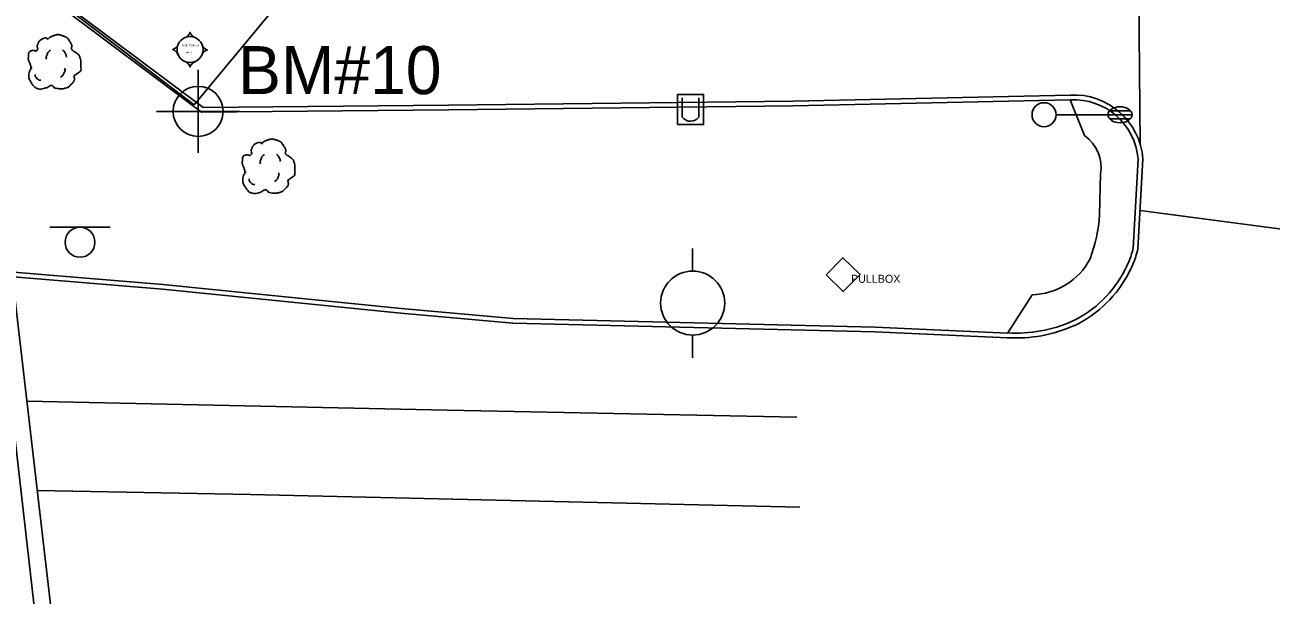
# Model space of a CAD drawing. Extents: x 2145380 to 2156929, y 139568 to 149130.
# Drawn here: x 2147386.4 to 2147542.1, y 143177.2 to 143248.5 of the extents above; entities that cross this region are included whole.
import ezdxf

# ---------------------------------------------------------------- set-up
doc = ezdxf.new("R2010")
doc.units = 0
for name, color, linetype in [('Default', 7, 'Continuous'), ('SURV_Benchmark', 7, 'Continuous'), ('SURV_Text', 7, 'Continuous'), ('TOPO_Asphalt', 7, 'Continuous'), ('TOPO_Concrete', 7, 'Continuous'), ('TOPO_Curb Back', 7, 'Continuous'), ('TOPO_Light Pole', 7, 'Continuous'), ('TOPO_Misc', 7, 'Continuous'), ('TOPO_Misc Line', 7, 'Continuous'), ('TOPO_Monitoring Well', 7, 'Continuous'), ('TOPO_Power Pole', 7, 'Continuous'), ('TOPO_Power Pullbox', 7, 'Continuous'), ('TOPO_Sidewalk', 7, 'Continuous'), ('TOPO_Sign', 7, 'Continuous'), ('TOPO_Tree', 7, 'Continuous')]:
    doc.layers.add(name, color=color, linetype=linetype)

# ---------------------------------------------------------------- blocks, each defined once
blk = doc.blocks.new('LP')
at = {"layer": 'TOPO_Light Pole'}
blk.add_line((3.81, 0), (20.32, 0), dxfattribs=at)
for points in [[(20.32, 0), (27.94, 0)], [(20.32, 0), (23.5, 0)], [(20.83, 1.27), (27.43, 1.27)], [(20.83, 1.27), (23.5, 1.27)], [(23.71, 1.27), (27.43, 1.27)], [(23.71, 0), (27.94, 0)], [(20.83, -1.27), (27.43, -1.27)], [(20.83, -1.27), (23.5, -1.27)], [(23.71, -1.27), (27.43, -1.27)]]:
    blk.add_lwpolyline(points, dxfattribs=at)
blk.add_circle((0, 0), 3.81, dxfattribs=at)
blk.add_ellipse((24.13, 0), major_axis=(3.81, 0), ratio=0.666667, dxfattribs=at)
blk = doc.blocks.new('TREE')
at = {"layer": 'TOPO_Tree'}
for points in [[(-14.07, -0.4), (-14.17, 0.5), (-14.37, 1.38), (-14.6, 2.25), (-14.84, 3.17), (-15.47, 3.96), (-15.66, 4.9), (-15.8, 5.59), (-15.71, 6.31), (-15.66, 7.01), (-15.6, 7.91), (-15.72, 8.8), (-15.13, 9.66), (-14.62, 10.42), (-13.76, 10.49), (-13.02, 10.72), (-12.18, 10.98), (-11.06, 10), (-10.37, 10.72), (-9.4, 11.74), (-10.29, 13.28), (-9.84, 14.42), (-9.56, 15.15), (-9.32, 15.89), (-8.78, 16.54), (-8.18, 17.26), (-7.5, 17.68), (-6.67, 18.13), (-6.14, 18.41), (-5.61, 18.61), (-5.08, 18.66), (-4.55, 18.71), (-4.02, 18.54), (-3.49, 18.13)], [(-3.49, 17.6), (-3.07, 18.27), (-2.58, 18.8), (-1.9, 19.19), (-1.05, 19.68), (-0.19, 19.96), (0.74, 20.24), (1.62, 20.51), (2.51, 20.82), (3.39, 20.77), (4.1, 20.73), (4.8, 20.47), (5.51, 20.24), (6.43, 19.95), (7.32, 19.73), (8.15, 19.19), (9.36, 18.4), (10.02, 17.21), (10.8, 16.01), (11.24, 15.33), (11.58, 14.62), (11.86, 13.89), (12.17, 13.08), (11.37, 12.02), (11.86, 11.25), (12, 11.03), (12.18, 10.86), (12.39, 10.72), (12.91, 10.35), (13.45, 10.02), (13.97, 9.66), (14.7, 9.16), (15.41, 8.68), (16.09, 8.07), (16.7, 7.53), (16.93, 6.73), (17.15, 5.95), (17.59, 4.38), (17.71, 2.77), (17.68, 1.19), (17.65, -0.25), (17.83, -2.22), (16.62, -3.04), (15.47, -3.83), (14.31, -4.58), (13.16, -5.35)], [(-4.21, 5.09), (-4.46, 6.09), (-4.3, 7.21), (-3.84, 8.21), (-3.33, 9.34), (-2.71, 10.27), (-1.64, 10.97)], [(5.89, 11.15), (6.5, 10.68), (6.96, 10.17), (7.36, 9.5), (7.93, 8.56), (8.31, 7.6), (8.46, 6.56)], [(13.16, -5.34), (13.25, -5.81), (13.36, -6.28), (13.45, -6.75), (13.76, -8.52), (12.24, -10.03), (10.8, -11.51), (9.98, -12.34), (9.13, -12.77), (8.15, -13.1), (5.97, -13.83), (3.32, -13.56), (1.27, -13.1), (0.49, -12.92), (-0.06, -11.44), (-0.84, -11.51), (-2.04, -11.61), (-3.28, -12.78), (-4.55, -13.1), (-6.06, -13.47), (-7.77, -14.03), (-9.31, -13.62), (-11.36, -13.09), (-12.84, -11.41), (-14.07, -9.39), (-15.32, -7.35), (-15.61, -5.13), (-15.13, -3.04), (-14.87, -1.89), (-13.91, -0.75), (-13.54, 0.13)], [(-11.38, -4.46), (-11.47, -5.41), (-11.03, -6.32), (-10.09, -7.22), (-9.3, -7.97), (-8.49, -8.26), (-7.7, -8.14)], [(4.79, -6.29), (5.71, -5.66), (6.3, -4.92), (6.81, -3.91), (7.36, -2.81), (7.63, -1.7), (7.54, -0.6)]]:
    blk.add_open_spline(points, degree=3, dxfattribs=at)
blk = doc.blocks.new('pulbox')
at = {"layer": 'Default'}
blk.add_lwpolyline([(-5.38, -0.01), (-0.02, 5.42), (5.4, 0.06), (0.05, -5.36), (-5.38, -0.01)], dxfattribs=at)
blk.add_text('PULLBOX', height=2.54, dxfattribs=at).set_placement((2.54, -2.54))
blk = doc.blocks.new('POWPOL')
at = {"layer": 'TOPO_Power Pole'}
for p, q in [((0, 10.16), (0, 17.34)), ((0, -10.16), (0, -17.34))]:
    blk.add_line(p, q, dxfattribs=at)
blk.add_circle((0, 0), 10.16, dxfattribs=at)
blk = doc.blocks.new('MONW')
at = {"layer": 'Default'}
for points in [[(-0.178, 0.372), (-0.138, 0.389), (-0.101, 0.407), (-0.063, 0.443), (-0.039, 0.474), (-0.018, 0.503), (-0.009, 0.523), (0.003, 0.552), (0.018, 0.515), (0.031, 0.488), (0.046, 0.47), (0.07, 0.441), (0.087, 0.425), (0.108, 0.407), (0.134, 0.396), (0.164, 0.385)], [(-0.369, 0.18), (-0.386, 0.141), (-0.405, 0.103), (-0.441, 0.066), (-0.471, 0.041), (-0.501, 0.021), (-0.52, 0.011), (-0.55, 0), (-0.513, -0.015), (-0.486, -0.028), (-0.467, -0.043), (-0.439, -0.068), (-0.422, -0.085), (-0.405, -0.106), (-0.394, -0.132), (-0.383, -0.162)], [(0.371, -0.189), (0.388, -0.149), (0.407, -0.111), (0.443, -0.074), (0.473, -0.05), (0.503, -0.029), (0.522, -0.019), (0.552, -0.008), (0.515, 0.007), (0.488, 0.02), (0.469, 0.035), (0.441, 0.06), (0.424, 0.077), (0.407, 0.098), (0.396, 0.124), (0.385, 0.154)], [(-0.178, -0.373), (-0.138, -0.39), (-0.101, -0.408), (-0.063, -0.444), (-0.039, -0.475), (-0.018, -0.504), (-0.009, -0.524), (0.003, -0.553), (0.018, -0.516), (0.031, -0.489), (0.046, -0.471), (0.07, -0.442), (0.087, -0.426), (0.108, -0.408), (0.134, -0.397), (0.164, -0.386)]]:
    blk.add_lwpolyline(points, dxfattribs=at)
blk.add_circle((0, 0), 0.413, dxfattribs=at)
for s, p in [('MONITORING', (-0.249, 0.103)), ('WELL', (-0.136, -0.124))]:
    blk.add_text(s, height=0.0607, dxfattribs=at).set_placement(p)
blk = doc.blocks.new('BM')
at = {"layer": 'SURV_Benchmark'}
for p, q in [((0, 2.49), (0, 4.15)), ((-2.49, 0), (-4.16, 0)), ((4.16, 0), (2.49, 0)), ((0, -4.16), (0, -2.49))]:
    blk.add_line(p, q, dxfattribs=at)
for points in [[(0, 2.49), (0, 2.49), (0, 0), (2.49, 0), (2.49, 0), (2.49, 0)], [(0, 2.49), (0, 2.49), (0, 0), (2.49, 0), (2.49, 0), (2.49, 0), (2.49, 0)], [(-2.5, 0), (-2.49, 0), (0, 0), (0, -2.49), (0, -2.49)], [(-2.5, 0), (-2.49, 0), (0, 0), (0, -2.49), (0, -2.49)]]:
    blk.add_lwpolyline(points, dxfattribs=at)
for start, end in [(90.0638, 180.0068), (0.0638, 90.0068), (0.0638, 90.0068), (180.0638, 270.0068), (180.0638, 270.0068), (269.9472, 359.9927)]:
    blk.add_arc((0, 0), 2.5, start, end, dxfattribs=at)

msp = doc.modelspace()

# ---------------------------------------------------------------- linework, layer by layer
at = {"layer": 'TOPO_Asphalt'}
for p, q in [((2147525.76, 143233.5), (2147525.28, 143281.26)), ((2147556.39, 143221.25), (2147525.73, 143225.25))]:
    msp.add_line(p, q, dxfattribs=at)
at = {"layer": 'TOPO_Concrete'}
msp.add_lwpolyline([(2147407.53, 143238.47), (2147436.9, 143273.89), (2147397.78, 143303.06), (2147368.44, 143268.23), (2147407.53, 143238.47)], dxfattribs=at)
at = {"layer": 'TOPO_Curb Back'}
for points in [[(2147517.02, 143239.1), (2147482.38, 143238.34), (2147439.31, 143237.85), (2147408.44, 143237.55), (2147377.76, 143260.51), (2147364.56, 143270.24), (2147354.31, 143301.63), (2147333.23, 143365.36), (2147326.82, 143385.52), (2147326.46, 143411.36), (2147326.23, 143416.01)], [(2147517, 143239.7), (2147482.37, 143238.94), (2147439.3, 143238.45), (2147408.63, 143238.16), (2147378.12, 143260.99), (2147365.07, 143270.61), (2147354.88, 143301.82), (2147333.8, 143365.55), (2147327.41, 143385.62), (2147327.06, 143411.38), (2147326.83, 143415.99)], [(2147525.46, 143220.46), (2147526.09, 143231.7)], [(2147524.87, 143220.55), (2147525.48, 143231.7)], [(2147377.36, 143218.18), (2147403.62, 143216.02), (2147433.38, 143213.03), (2147447.37, 143211.78), (2147492.61, 143210.69), (2147509.18, 143209.95)], [(2147377.31, 143217.58), (2147403.56, 143215.42), (2147433.33, 143212.43), (2147447.34, 143211.18), (2147492.58, 143210.09), (2147509.15, 143209.36)]]:
    msp.add_lwpolyline(points, dxfattribs=at)
for centre, radius, start, end in [((2147517.47, 143231.07), 8.64, 4.2214, 93.1405), ((2147517.47, 143231.07), 8.04, 4.4927, 93.21), ((2147514.98, 143222.78), 10.13, 331.1748, 347.2659), ((2147514.98, 143222.78), 10.73, 331.2331, 347.5376), ((2147511.03, 143224.36), 14.37, 295.7068, 333.2536), ((2147511.03, 143224.36), 14.97, 295.6687, 333.2121), ((2147510.2, 143227.42), 18.09, 266.6586, 293.8423), ((2147510.2, 143227.42), 17.49, 266.645, 293.8109)]:
    msp.add_arc(centre, radius, start, end, dxfattribs=at)
at = {"layer": 'TOPO_Misc'}
for p, q in [((2147468.52, 143239.33), (2147468.52, 143236.92)), ((2147470.6, 143236.93), (2147470.6, 143239.34))]:
    msp.add_line(p, q, dxfattribs=at)
msp.add_lwpolyline([(2147467.93, 143236.01), (2147467.93, 143239.77), (2147471.19, 143239.77), (2147471.19, 143236.01), (2147467.93, 143236.01)], dxfattribs=at)
msp.add_arc((2147469.56, 143237.74), 1.32, 218.3412, 322.0625, dxfattribs=at)
at = {"layer": 'TOPO_Misc Line'}
msp.add_lwpolyline([(2147389.93, 143172.79), (2147385.03, 143215.16), (2147383.04, 143214.93), (2147388.02, 143171.39)], close=True, dxfattribs=at)
for points in [[(2147386.62, 143201.42), (2147439.12, 143200.3), (2147482.85, 143199.43)], [(2147387.91, 143190.27), (2147414.57, 143189.75), (2147483.2, 143188.18)]]:
    msp.add_lwpolyline(points, dxfattribs=at)
at = {"layer": 'TOPO_Sidewalk'}
for points in [[(2147518.79, 143234.64), (2147517.02, 143239.1)], [(2147520.67, 143224.73), (2147520.81, 143229.84)], [(2147509.19, 143209.96), (2147512.23, 143214.73)]]:
    msp.add_lwpolyline(points, dxfattribs=at)
for centre, radius, start, end in [((2147515.92, 143230.61), 4.95, 351.0576, 54.5152), ((2147500.9, 143226.1), 19.82, 339.7517, 356.026), ((2147512.04, 143223.15), 8.42, 271.3381, 332.3506)]:
    msp.add_arc(centre, radius, start, end, dxfattribs=at)
at = {"layer": 'TOPO_Sign'}
for points in [[(2147389.5, 143223.17), (2147397, 143223.17)], [(2147393.25, 143223.17), (2147393.25, 143223.17)], [(2147391.38, 143221.3), (2147391.38, 143221.3)], [(2147395.12, 143221.3), (2147395.12, 143221.3)], [(2147393.25, 143219.43), (2147393.25, 143219.43)]]:
    msp.add_lwpolyline(points, dxfattribs=at)
for start, end in [(90, 180), (360, 90), (180, 270), (270, 0)]:
    msp.add_arc((2147393.25, 143221.3), 1.87, start, end, dxfattribs=at)

# ---------------------------------------------------------------- block references
at = {"layer": 'SURV_Benchmark', "xscale": 1.25, "yscale": 1.25}
msp.add_blockref('BM', (2147408.01, 143237.66), dxfattribs=at)
at = {"layer": 'TOPO_Light Pole', "xscale": 0.39370000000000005, "yscale": 0.3937000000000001}
msp.add_blockref('LP', (2147513.73, 143237.24), dxfattribs=at)
at = {"layer": 'TOPO_Monitoring Well', "xscale": 3.9370000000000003, "yscale": 3.9370000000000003}
msp.add_blockref('MONW', (2147407, 143245.38), dxfattribs=at)
at = {"layer": 'TOPO_Power Pole', "xscale": 0.39370000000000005, "yscale": 0.3937000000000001}
msp.add_blockref('POWPOL', (2147469.82, 143213.69), dxfattribs=at)
at = {"layer": 'TOPO_Power Pullbox', "xscale": 0.39370000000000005, "yscale": 0.3937000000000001}
msp.add_blockref('pulbox', (2147488.61, 143217.23), dxfattribs=at)
at = {"layer": 'TOPO_Tree', "xscale": 0.19685000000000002, "yscale": 0.19685000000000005}
for p in [(2147389.89, 143243.16), (2147416.63, 143230.11)]:
    msp.add_blockref('TREE', p, dxfattribs=at)

# ---------------------------------------------------------------- texts
at = {"layer": 'SURV_Text'}
msp.add_text('BM#10', height=6, dxfattribs=at).set_placement((2147413.01, 143239.81))

doc.saveas('drawing.dxf')
